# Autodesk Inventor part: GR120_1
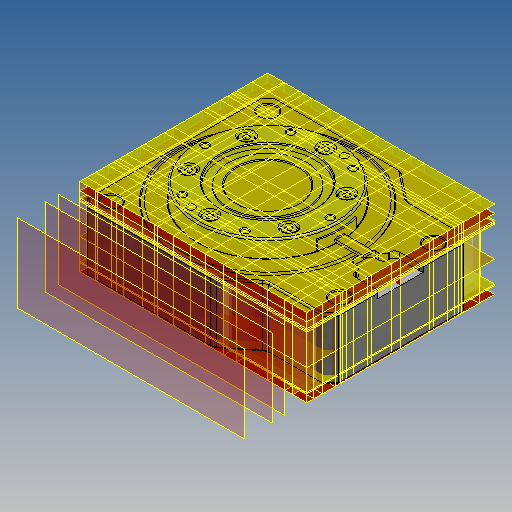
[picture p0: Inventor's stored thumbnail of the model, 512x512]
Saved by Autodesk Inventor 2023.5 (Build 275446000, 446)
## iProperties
Part Number: GR120_1
Material: Allgemein
Document SubType Name: Modellieren
Designer: WH
Appearance: Vorgabe
Author: WH
NB: GR120_1
NN: GR120
NBSYN: $CNSORDERNO._1
LINA: GR120_1
CATALOG: GIGAGER
CNSORDERNO: GR120
SCS: GR120
SUPPLIER: SAINI
ARTICLENO: GR120_1
BOMINFO: GR120_1
CREATOR: CADENAS GmbH
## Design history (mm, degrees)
feature "GR120_1"
feature "Zusammengesetzt1"
node "A_1"
node "A_2"
node "A_3"
node "A_4"
node "A_5"
node "A_6"
node "A_7"
node "A_8"
node "A_9"
node "A_10"
node "A_11"
node "A_12"
node "A_13"
node "A_14"
node "A_15"
node "A_16"
node "A_17"
node "A_18"
node "A_19"
node "A_20"
node "A_21"
node "A_22"
node "A_23"
node "A_24"
node "A_25"
node "A_26"
node "A_27"
node "A_28"
node "A_29"
node "A_30"
node "A_31"
node "A_32"
node "A_33"
node "A_34"
node "A_35"
node "A_36"
node "A_37"
node "A_38"
node "A_39"
node "A_40"
node "A_41"
node "A_42"
node "A_43"
node "A_44"
node "A_45"
node "A_46"
node "A_47"
node "A_48"
node "A_49"
node "A_50"
node "A_51"
node "A_52"
node "A_53"
node "A_54"
node "A_55"
node "A_56"
node "A_57"
node "A_58"
node "A_59"
node "A_60"
node "A_61"
node "A_62"
node "A_63"
node "A_64"
node "1_ZAXS"
node "RIGHT"
node "TOP"
node "FRONT"
node "DTM1"
node "DTM2"
node "DTM3"
node "DTM4"
node "DTM5"
node "DTM6"
node "DTM7"
node "DTM8"
node "DTM9"
node "DTM10"
node "DTM11"
node "DTM12"
node "DTM13"
node "DTM14"
node "DTM15"
node "DTM16"
node "DTM17"
node "DTM18"
node "DTM19"
node "DTM20"
node "DTM21"
node "DTM22"
node "DTM23"
node "DTM24"
node "DTM25"
node "DTM26"
node "DTM27"
node "DTM28"
node "DTM29"
node "DTM30"
node "DTM31"
node "DTM32"
node "DTM33"
node "DTM34"
node "DTM35"
node "DTM36"
node "DTM37"
node "DTM38"
node "DTM39"
node "DTM40"
node "DTM41"
node "DTM42"
node "DTM43"
node "DTM44"
node "DTM45"
node "DTM46"
node "DTM47"
node "DTM48"
node "DTM49"
node "DTM50"
node "DTM51"
node "DTM52"
node "DTM53"
node "DTM54"
node "DTM55"
node "DTM56"
node "DTM57"
node "DTM58"
node "DTM59"
node "DTM60"
node "DTM61"
node "DTM62"
node "DTM63"
node "DTM64"
node "DTM65"
node "DTM66"
node "DTM67"
node "DTM68"
node "DTM69"
node "DTM70"
node "DTM71"
node "DTM72"
node "DTM73"
node "DTM74"
node "DTM75"
node "DTM76"
node "DTM77"
node "DTM78"
node "DTM79"
node "DTM80"
node "DTM81"
node "DTM82"
node "DTM83"
node "DTM84"
node "DTM85"
node "DTM86"
node "DTM87"
node "DTM88"
node "DTM89"
node "DTM90"
node "DTM91"
node "DTM92"
node "DTM93"
node "DTM94"
node "DTM95"
node "DTM96"
node "DTM97"
node "DTM98"
node "DTM99"
node "DTM100"
node "DTM101"
node "DTM102"
node "DTM103"
node "DTM104"
node "DTM105"
node "DTM106"
node "DTM107"
node "DTM108"
node "DTM109"
node "DTM110"
node "DTM111"
node "DTM112"
node "DTM113"
node "DTM114"
node "DTM115"
node "DTM116"
node "DTM117"
node "DTM118"
node "DTM119"
node "DTM120"
node "DTM121"
node "DTM122"
node "DTM123"
node "DTM124"
node "DTM125"
node "DTM126"
node "DTM127"
node "DTM128"
node "DTM129"
node "DTM130"
node "DTM131"
node "DTM132"
node "DTM133"
node "DTM134"
node "DTM135"
node "DTM136"
node "DTM137"
node "DTM138"
node "DTM139"
node "DTM140"
node "DTM141"
node "DTM142"
node "DTM143"
node "DTM144"
node "DTM145"
node "1_XPLN"
node "1_YPLN"
node "1_ZPLN"
node "Volumenkörper1"
node "Volumenkörper"
node "Flächenkörper"
node "Flä1"
